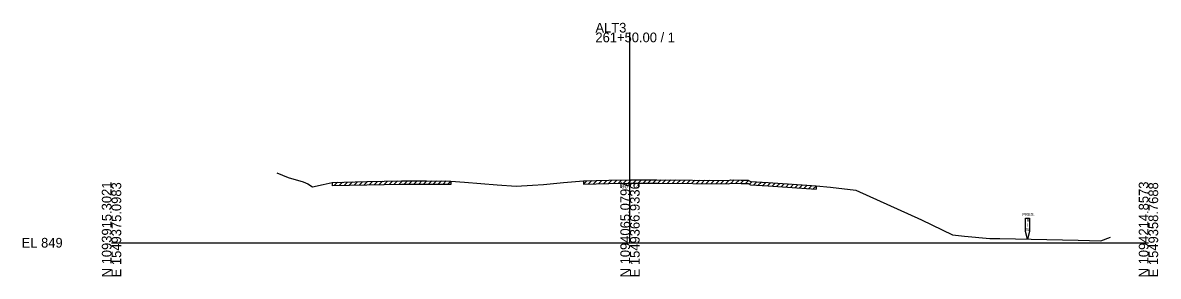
# Model space of a CAD drawing. Extents: x -26 to 1303, y -10 to 19582.
# Drawn here: x 974.3 to 1302.8, y 14990.3 to 15063.6 of the extents above; entities that cross this region are included whole.
import ezdxf

# ---------------------------------------------------------------- set-up
doc = ezdxf.new("R2010")
doc.units = 0
for name, color, linetype in [('Default', 7, 'Continuous'), ('RD_GPK_XS_Cell', 7, 'Continuous'), ('RD_XS_ExGround', 7, 'Continuous'), ('RD_XS_ExPaveRet', 7, 'Continuous'), ('RD_XS_ExRW', 7, 'Continuous'), ('RD_XS_TX_Elev_EX', 7, 'Continuous')]:
    doc.layers.add(name, color=color, linetype=linetype)

msp = doc.modelspace()

# ---------------------------------------------------------------- linework, layer by layer
at = {"layer": 'RD_GPK_XS_Cell'}
for p, q in [((1150, 15000), (1150, 15060.76)), ((1000, 15000), (1150, 15000)), ((1150, 15000), (1300, 15000))]:
    msp.add_line(p, q, dxfattribs=at)
at = {"layer": 'RD_XS_ExGround'}
msp.add_lwpolyline([(1047.86, 15020.25), (1051.13, 15018.86), (1055.46, 15017.56), (1056.81, 15016.98), (1058.17, 15016.19), (1061.22, 15016.82), (1063.85, 15017.45), (1073.91, 15017.67), (1083.85, 15017.89), (1091.08, 15017.88), (1098.21, 15017.84), (1102.16, 15017.49), (1111.54, 15016.71), (1117.11, 15016.39), (1121.77, 15016.61), (1125.02, 15016.87), (1130.81, 15017.46), (1136.54, 15017.92), (1143.84, 15018.04), (1149.95, 15018.14), (1157.77, 15018.2), (1178.54, 15017.97), (1179.2, 15018.2), (1182.21, 15018.09), (1184.22, 15018.04), (1184.89, 15017.73), (1189.94, 15017.37), (1203.86, 15016.46), (1208.05, 15016.03), (1215.35, 15015.15), (1234.32, 15006.58), (1243.26, 15002.28), (1246.81, 15001.92), (1254.11, 15001.27), (1257.03, 15001.25), (1279.65, 15000.73), (1286.19, 15000.59), (1288.97, 15001.65)], dxfattribs=at)
at = {"layer": 'RD_XS_ExPaveRet'}
for p, q in [((1063.85, 15017.45), (1063.85, 15016.45)), ((1063.85, 15017.36), (1063.93, 15017.45)), ((1064.41, 15016.51), (1065.38, 15017.48)), ((1065.86, 15016.54), (1066.83, 15017.51)), ((1067.3, 15016.57), (1068.27, 15017.55)), ((1068.75, 15016.61), (1069.72, 15017.58)), ((1070.19, 15016.64), (1071.17, 15017.61)), ((1071.64, 15016.67), (1072.61, 15017.64)), ((1073.09, 15016.7), (1074.06, 15017.67)), ((1074.53, 15016.73), (1075.5, 15017.71)), ((1075.98, 15016.77), (1076.95, 15017.74)), ((1077.43, 15016.8), (1078.4, 15017.77)), ((1078.87, 15016.83), (1079.84, 15017.8)), ((1080.32, 15016.86), (1081.29, 15017.83)), ((1081.76, 15016.89), (1082.74, 15017.87)), ((1083.21, 15016.93), (1084.17, 15017.89)), ((1084.64, 15016.94), (1085.59, 15017.89)), ((1086.05, 15016.94), (1087, 15017.89)), ((1087.46, 15016.94), (1088.41, 15017.89)), ((1088.88, 15016.94), (1089.82, 15017.88)), ((1090.29, 15016.93), (1091.24, 15017.88)), ((1091.7, 15016.93), (1092.64, 15017.87)), ((1093.1, 15016.92), (1094.05, 15017.87)), ((1094.51, 15016.91), (1095.46, 15017.86)), ((1095.92, 15016.91), (1096.86, 15017.85)), ((1097.32, 15016.9), (1098.21, 15017.78)), ((1098.21, 15017.84), (1098.21, 15016.84)), ((1136.54, 15017.92), (1136.54, 15016.92)), ((1136.56, 15016.97), (1137.52, 15017.94)), ((1138, 15017), (1138.96, 15017.96)), ((1139.43, 15017.02), (1140.4, 15017.99)), ((1140.87, 15017.04), (1141.84, 15018.01)), ((1142.31, 15017.07), (1143.27, 15018.03)), ((1143.75, 15017.09), (1144.71, 15018.06)), ((1145.18, 15017.11), (1146.15, 15018.08)), ((1146.62, 15017.14), (1147.59, 15018.1)), ((1148.06, 15017.16), (1149.02, 15018.13)), ((1149.5, 15017.18), (1150.46, 15018.14)), ((1150.93, 15017.2), (1151.88, 15018.16)), ((1152.35, 15017.21), (1153.31, 15018.17)), ((1153.78, 15017.22), (1154.74, 15018.18)), ((1155.2, 15017.23), (1156.16, 15018.19)), ((1156.63, 15017.25), (1157.59, 15018.2)), ((1158.05, 15017.25), (1158.99, 15018.19)), ((1159.45, 15017.24), (1160.39, 15018.18)), ((1160.85, 15017.22), (1161.79, 15018.16)), ((1162.25, 15017.21), (1163.19, 15018.14)), ((1163.65, 15017.19), (1164.59, 15018.13)), ((1165.04, 15017.17), (1165.98, 15018.11)), ((1166.44, 15017.16), (1167.38, 15018.1)), ((1167.84, 15017.14), (1168.78, 15018.08)), ((1169.24, 15017.13), (1170.18, 15018.07)), ((1170.64, 15017.11), (1171.58, 15018.05)), ((1172.04, 15017.1), (1172.98, 15018.04)), ((1173.44, 15017.08), (1174.38, 15018.02)), ((1174.84, 15017.07), (1175.77, 15018.01)), ((1176.23, 15017.05), (1177.17, 15017.99)), ((1177.63, 15017.03), (1178.59, 15017.99)), ((1179.26, 15017.25), (1180.18, 15018.17)), ((1180.63, 15017.2), (1181.54, 15018.12)), ((1181.99, 15017.15), (1182.91, 15018.07)), ((1183.37, 15017.11), (1184.27, 15018.02)), ((1184.59, 15016.92), (1185.37, 15017.7)), ((1185.8, 15016.72), (1186.69, 15017.6)), ((1187.12, 15016.62), (1188.01, 15017.51)), ((1188.44, 15016.53), (1189.33, 15017.42)), ((1189.76, 15016.44), (1190.65, 15017.33)), ((1191.09, 15016.35), (1191.98, 15017.24)), ((1192.41, 15016.26), (1193.31, 15017.15)), ((1193.74, 15016.17), (1194.63, 15017.07)), ((1195.07, 15016.09), (1195.96, 15016.98)), ((1196.4, 15016), (1197.29, 15016.89)), ((1197.72, 15015.91), (1198.62, 15016.81)), ((1199.05, 15015.83), (1199.94, 15016.72)), ((1200.38, 15015.74), (1201.27, 15016.63)), ((1201.71, 15015.65), (1202.6, 15016.54)), ((1203.03, 15015.57), (1203.86, 15016.39)), ((1203.86, 15016.46), (1203.86, 15015.46))]:
    msp.add_line(p, q, dxfattribs=at)
for points in [[(1136.54, 15016.97), (1143.84, 15017.09), (1149.95, 15017.19), (1157.77, 15017.25), (1178.54, 15017.02), (1179.2, 15017.25), (1182.21, 15017.14), (1184.22, 15017.09), (1184.89, 15016.78), (1189.94, 15016.42), (1203.86, 15015.51)], [(1063.85, 15016.5), (1063.85, 15016.5), (1073.91, 15016.72), (1083.85, 15016.94), (1091.08, 15016.93), (1098.21, 15016.89)]]:
    msp.add_lwpolyline(points, dxfattribs=at)
at = {"layer": 'RD_XS_ExRW'}
msp.add_lwpolyline([(1264.46, 15007.08), (1265.56, 15007.08), (1265.56, 15003.26), (1265.01, 15001.07), (1264.46, 15003.26)], close=True, dxfattribs=at)

# ---------------------------------------------------------------- texts
at = {"layer": 'Default'}
msp.add_text('-', height=0.0001, dxfattribs=at).set_placement((1000, 15000))
at = {"layer": 'RD_GPK_XS_Cell'}
for s, p in [('ALT3', (1140, 15060.76)), ('261+50.00 / 1', (1140, 15057.96)), ('EL 849', (974, 14998.6))]:
    msp.add_text(s, height=2.8, dxfattribs=at).set_placement(p)
for s, p in [('N 1093915.3021', (1000, 14990)), ('E 1549375.0983', (1002.8, 14990)), ('N 1094065.0797', (1150, 14990)), ('E 1549366.9336', (1152.8, 14990)), ('N 1094214.8573', (1300, 14990)), ('E 1549358.7688', (1302.8, 14990))]:
    msp.add_text(s, height=2.8, rotation=90, dxfattribs=at).set_placement(p)
at = {"layer": 'RD_XS_ExRW'}
for s, p in [('PRES.', (1263.46, 15007.71)), ('W', (1264.54, 15003.37)), ('R', (1264.72, 15005.99)), ('/', (1264.85, 15004.68))]:
    msp.add_text(s, height=0.875, dxfattribs=at).set_placement(p)
at = {"layer": 'RD_XS_TX_Elev_EX'}
msp.add_text('867.14', height=1.25, dxfattribs=at).set_placement((1147.44, 15015.72))

doc.saveas('drawing.dxf')
